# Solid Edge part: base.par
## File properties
Title: Base
Author: Abhinav Rai
Template: Normal.par
Last saved by: Cadcim
Revision: 24
Application: Solid Edge
Material: aluminum
Accuracy: 0.99
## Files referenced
..\Asm2.asm
/D:\solid_edge_18\c09_sld_edg_18_030606\Asm2.asm
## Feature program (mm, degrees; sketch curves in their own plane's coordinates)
sketch for "unnamed Protrusion 1" plane through (0, 0, 0) normal (1, 0, 0) x-axis (0, 1, 0)
  line (-34.925, 42.0624) -> (-34.925, -42.0624)
  line (-15.875, -42.0624) -> (-34.925, -42.0624)
  line (-15.875, -42.0624) -> (-15.875, -15.0876)
  line (-15.875, -15.0876) -> (-12.7, -15.0876)
  line (-12.7, -15.0876) -> (-12.7, 0.8001)
  line (-12.7, 0.8001) -> (12.7, 0.8001)
  line (12.7, 0.8001) -> (12.7, -15.0876)
  line (12.7, -15.0876) -> (15.875, -15.0876)
  line (15.875, -15.0876) -> (15.875, -42.0624)
  line (15.875, -42.0624) -> (34.925, -42.0624)
  line (34.925, -42.0624) -> (34.925, 42.0624)
  line (34.925, 42.0624) -> (-34.925, 42.0624)
  dimension (linear) = 15.875
extrude "unnamed Protrusion 1" add finite 184.15 along -normal
sketch for "unnamed Cutout 1" plane through (-92.075, -34.925, 0) normal (0, -1, 0) x-axis (1, 0, 0)
  line (-60.325, 58.9033) -> (-60.325, -2.3876)
  line (-60.325, -2.3876) -> (66.675, -2.3876)
  line (66.675, -2.3876) -> (66.675, 32.5374)
  line (66.675, 32.5374) -> (138.7184, 32.5374)
  line (138.7184, 32.5374) -> (138.7184, 58.9033)
  line (-60.325, 58.9033) -> (138.7184, 58.9033)
extrude "unnamed Cutout 1" cut through along -normal
sketch for "ExtrudedCutout_2" plane through (0, 0, -4.3434) normal (1, 0, 0) x-axis (0, 1, 0)
  line (18.2179, 17.8308) -> (34.925, 17.8308)
  line (42.2755, 17.8308) -> (34.925, 17.8308)
  line (42.2755, 51.2375) -> (42.2755, 17.8308)
  line (-47.5259, 51.2375) -> (42.2755, 51.2375)
  line (-47.5259, 17.8308) -> (-47.5259, 51.2375)
  line (-34.925, 17.8308) -> (-47.5259, 17.8308)
  line (-34.925, 17.8308) -> (-18.2179, 17.8308)
  arc centre (0, 18.6448) radius 18.236 from (-18.2179, 17.8308) to (18.2179, 17.8308) cw
extrude "ExtrudedCutout_2" cut finite 76.2 along -normal
sketch for "Hole_1" plane through (0, 0, -4.7625) normal (1, 0, 0) x-axis (0, 1, 0)
  hole centre (0, 19.0639) bore radius 7.9375
hole "Hole_1" diameter 15.875 through
fillet "Round_2" radius 34.925
sketch for "ExtrudedProtrusion_2" plane through (-92.075, -25.4, -42.0624) normal (0, 0, -1) x-axis (1, 0, 0)
  arc centre (63.5638, -62.2328) radius 28.575 from (92.075, -60.325) to (35.0525, -60.325) cw
  line (35.4, -60.325) -> (92.075, -60.325)
extrude "ExtrudedProtrusion_2" add finite 7.9248 along -normal
sketch for "Hole_2" plane through (-31.5444, 50.1664, -34.1376) normal (0, 0, 1) x-axis (-1, 0, 0)
hole "Hole_2" diameter 7.9248 through
mirror "unnamed Mirror 1" of "ExtrudedProtrusion_2", "Hole_2" about plane through (-92.075, 0, 0) normal (1, 0, 0)
extrude "unnamed Protrusion 2" add finite 7.9248
hole "unnamed Hole 1" through
mirror "unnamed Mirror 2" of "ExtrudedProtrusion_2", "Hole_2", "unnamed Mirror 1" about plane through (0, 0, 0) normal (0, -1, 0)
extrude "unnamed Protrusion 3" add finite 7.9248
hole "unnamed Hole 2" through
extrude "unnamed Protrusion 4" add finite 7.9248
hole "unnamed Hole 3" through
sketch for "Hole_28" plane through (-152.4, 0, 15.5518) normal (1, 0, 0) x-axis (0, 1, 0)
  hole centre (19.05, 7.4606) bore radius 3.175
hole "Hole_28" diameter 6.35 finite
sketch for "unnamed Hole 4" plane through (-152.4, 0, 15.5518) normal (1, 0, 0) x-axis (0, 1, 0)
  hole centre (-19.05, 7.4606) bore radius 3.175
  dimension (linear) = 19.05
  dimension (linear) = 19.05
hole "unnamed Hole 4" finite
pattern "unnamed Pattern 1" of "Hole_28", "unnamed Hole 4"
fillet "Round_24" radius 3.81
hole "Hole_30" diameter 6.35 through
hole "unnamed Hole 5" through
hole "unnamed Hole 6" through
pattern "unnamed Pattern 2" of "Hole_30", "unnamed Hole 5", "unnamed Hole 6"
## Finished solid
Body 1: solid body, 94 faces, 227 edges, 122 vertices.
  Faces by surface: cylinder 41, plane 26, torus 13, blend 12, sphere 2
  Edges by curve: circle 105, line 96, intersection 26
Bounding box of the edges (mm; curved faces can reach further): 184.280 x 130.816 x 84.125, from (-184.2151, -65.4078, -42.0624) to (0.0651, 65.4078, 42.0624).
Cylindrical faces by radius (mm): R3.175 x8, R3.81 x22, R3.9624 x4, R7.9375 x1, R18.236 x1, R28.575 x4, R34.925 x1
Toroidal faces (ring radius, tube radius in mm): R7.62 r3.81 x6, R14.426 r3.81 x1, R24.765 r3.81 x4, R31.115 r3.81 x2
Spherical faces by radius (mm): R3.81 x2
Planar faces by outward normal: +x 4, +y 3, +z 8, -x 2, -y 3, -z 6
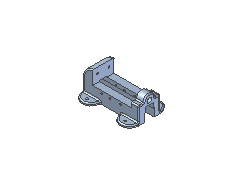
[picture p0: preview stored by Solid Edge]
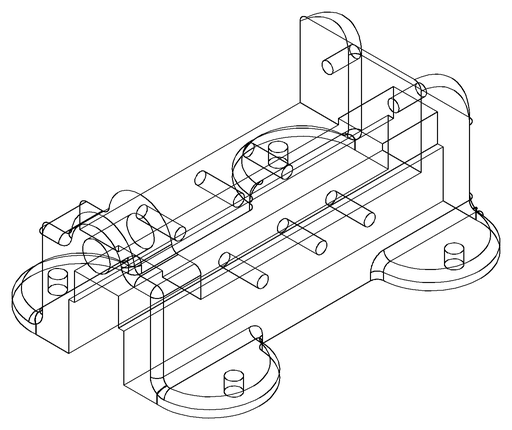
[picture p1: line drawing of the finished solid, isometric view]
